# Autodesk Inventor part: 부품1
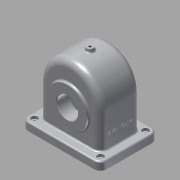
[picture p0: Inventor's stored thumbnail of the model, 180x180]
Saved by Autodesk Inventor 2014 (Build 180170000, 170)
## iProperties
Created: 2016-10
Part Number: 부품1
Material: 알루미늄 6061
Document SubType Name: Modeling
Designer: SCD-A13
Density: 2.71 g/cm^3
Appearance: 알루미늄 - 평지
Mass: 1172.89 g
Surface Area: 1200.96 cm^2
Volume: 432.802 cm^3
Author: SCD-A13
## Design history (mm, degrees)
sketch "스케치1"
  geometry: L1 (75, 55)-(-75, 55); L2 (-75, 55)-(-75, -55); L3 (-75, -55)-(75, -55); L4 (75, -55)-(75, 55); L5 (75, 55)-(-75, -55); L6 (-75, 55)-(75, -55); 1 further point
  constraints: 12 end point, 2 midpoint, 2 parallel, 1 horizontal, 1 perpendicular
  dimensions: "d0" = 150 distance of L2.end L3.end; "d1" = 110 distance of L3.end L1.start
extrude "돌출1" new body sketch "스케치1" distance "d2" = 15; taper "d3" = 0 deg
sketch "스케치2"
  geometry: L1 (75, 15)-(-75, 15) reference; L2 (-58, 80)-(-58, 15); L3 (-75, 0)-(-75, 15) reference; L4 (58, 80)-(58, 15); L5 (75, 0)-(-75, 0) reference; A1 r 58 centre (0, 80) between (-58, 80) and (58, 80); 2 further points
  constraints: 4 end point, 2 point on circle, 2 point on line, 2 tangent, 1 centre point, 1 midpoint, 1 parallel, 1 perpendicular, 1 vertical alignment
  dimensions: "d4" = 116 diameter of A1; "d5" = 80 distance from line of L5 A1.centre
extrude "돌출2" join sketch "스케치2" stored distance "d6" = 77; taper "d7" = 0 deg
fillet "모깎기1" dims "d8" = 13
sketch "스케치3"
  geometry: L1 (52, 80)-(52, 0); L2 (-52, 80)-(-52, 0); L3 (-58, 15)-(-58, 80) reference; L4 (-52, 0)-(52, 0); L5 (75, 0)-(-75, 0) reference; A1 r 52 centre (0, 80) between (52, 80) and (-52, 80); A2 r 58 centre (0, 80) between (58, 80) and (-58, 80) reference; 1 further point
  constraints: 6 end point, 2 point on circle, 2 tangent, 1 centre point, 1 coincident, 1 collinear, 1 parallel, 1 perpendicular, 1 vertical, 1 vertical alignment
  dimensions: "d9" = 104 diameter of A1
extrude "돌출3" cut sketch "스케치3" stored distance "d11" = 67; taper "d12" = 0 deg
fillet "모깎기2" dims "d13" = 8
node "작업 평면1"
sketch "스케치4"
  geometry: C1 r 28 at (0, 65); 1 further point
  constraints: 1 centre point
  dimensions: "d15" = 56 diameter of C1; "d16" = 65 distance of point (0, 0) C1.centre
extrude "돌출4" join sketch "스케치4" stored distance "d17" = 67; taper "d18" = 40 deg
sketch "스케치5"
  geometry: L1 (-75, 0)-(75, 0) reference; C1 r 37.5 at (0, 65); 1 further point
  constraints: 1 centre point
  dimensions: "d19" = 75 diameter of C1; "d20" = 65 distance from line of L1 C1.centre
extrude "돌출5" join sketch "스케치5" distance "d21" = 5; taper "d22" = 0 deg
sketch "스케치6"
  geometry: L1 (-75, 0)-(75, 0) reference; C1 r 31 at (0, 65); 1 further point
  constraints: 1 centre point
  dimensions: "d23" = 62 diameter of C1; "d24" = 65 distance from line of L1 C1.centre
extrude "돌출6" join sketch "스케치6" distance "d25" = 10; taper "d26" = 0 deg
hole "구멍1" diameter "d29" = 40; stored, may be unused: countersink angle "d33" = 90 deg, drill point angle "d35" = 118 deg; dims "d27" = 10, "d28" = 10, "d30" = 6, "d31" = 4, "d32" = 2, "d34" = 8
node "작업 평면2"
sketch "스케치8"
  geometry: C1 r 6 at (0, 0); 1 further point
  constraints: 1 centre point, 1 coincident
  dimensions: "d37" = 12 diameter of C1
extrude "돌출7" join sketch "스케치8" stored distance "d38" = 10; taper "d39" = 10 deg
fillet "모깎기3" dims "d40" = 3
hole "구멍2" diameter "d43" = 4.459; stored, may be unused: countersink angle "d47" = 90 deg, drill point angle "d49" = 118 deg; dims "d41" = 10, "d42" = 10, "d44" = 6, "d45" = 4, "d46" = 2, "d48" = 8
chamfer "모따기1" distance "d50" = 1; stored, may be unused: second distance "d51" = 2, angle "d52" = 45 deg
fillet "모깎기4" dims "d53" = 12
fillet "모깎기5" dims "d54" = 3
sketch "스케치9"
  geometry: A1 r 9 centre (-63, 43) between (-63, 52) and (-72, 43) reference; A2 r 9 centre (-63, -43) between (-72, -43) and (-63, -52) reference; A3 r 9 centre (63, -43) between (63, -52) and (72, -43) reference; A4 r 9 centre (63, 43) between (72, 43) and (63, 52) reference; 5 further points
  constraints: 4 coincident
hole "구멍3" sketch "스케치9" at (-63, 43), (63, 43), (63, -43), (-63, -43) diameter "d55" = 5; stored, may be unused: countersink angle "d59" = 90 deg, drill point angle "d61" = 118 deg; dims "d56" = 6, "d57" = 12, "d58" = 5, "d60" = 8
sketch "스케치10" dims "d62" = 52
  geometry: C1 r 31 at (0, 0) reference; C2 r 21 at (0, 0) reference; 3 further points
  constraints: 2 vertical alignment, 1 coincident, 2 other
hole "구멍4" sketch "스케치10" at (0, 26) diameter "d63" = 2.459; stored, may be unused: countersink angle "d67" = 90 deg, drill point angle "d69" = 118 deg; dims "d64" = 6, "d65" = 12, "d66" = 5, "d68" = 8
sketch "스케치11" dims "d73" = 58
  geometry: C1 r 37.5 at (0, 0) reference; C2 r 21 at (0, 0) reference; 3 further points
  constraints: 2 vertical alignment, 1 coincident, 2 other
hole "구멍5" sketch "스케치11" at (0, 29) diameter "d74" = 2.459; stored, may be unused: countersink angle "d78" = 90 deg, drill point angle "d80" = 118 deg; dims "d75" = 6, "d76" = 12, "d77" = 5, "d79" = 8
sketch "스케치12"
  geometry: L1 (-17.5, -80)-(-29.5, -80) reference; L2 (-13, 0)-(-13, -62) reference; 2 further points
  constraints: 1 other
  dimensions: "d84" = 40 distance from line of L1 point (25.5, -40); "d85" = 38.5 distance from line of L2 point (25.5, -40)
feature "엠보싱1" sketch "스케치12" dims "d0" = 150, "d1" = 110, "d8" = 13, "d86" = 0.5, "d87" = 0
node "솔리드1"
pattern_circular "원형 패턴1" dims angle "d71" = 360 deg
pattern_circular "원형 패턴2" dims angle "d82" = 360 deg
other parameters: "d14" = 14, "d36" = 144
